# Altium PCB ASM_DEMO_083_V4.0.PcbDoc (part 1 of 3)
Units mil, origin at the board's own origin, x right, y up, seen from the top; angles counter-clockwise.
Board outline 4534.65 x 3225.59 mil, 2 copper layers (Top Layer, Bottom Layer); 192 components, 109 nets, 496 pads, 1295 vias.
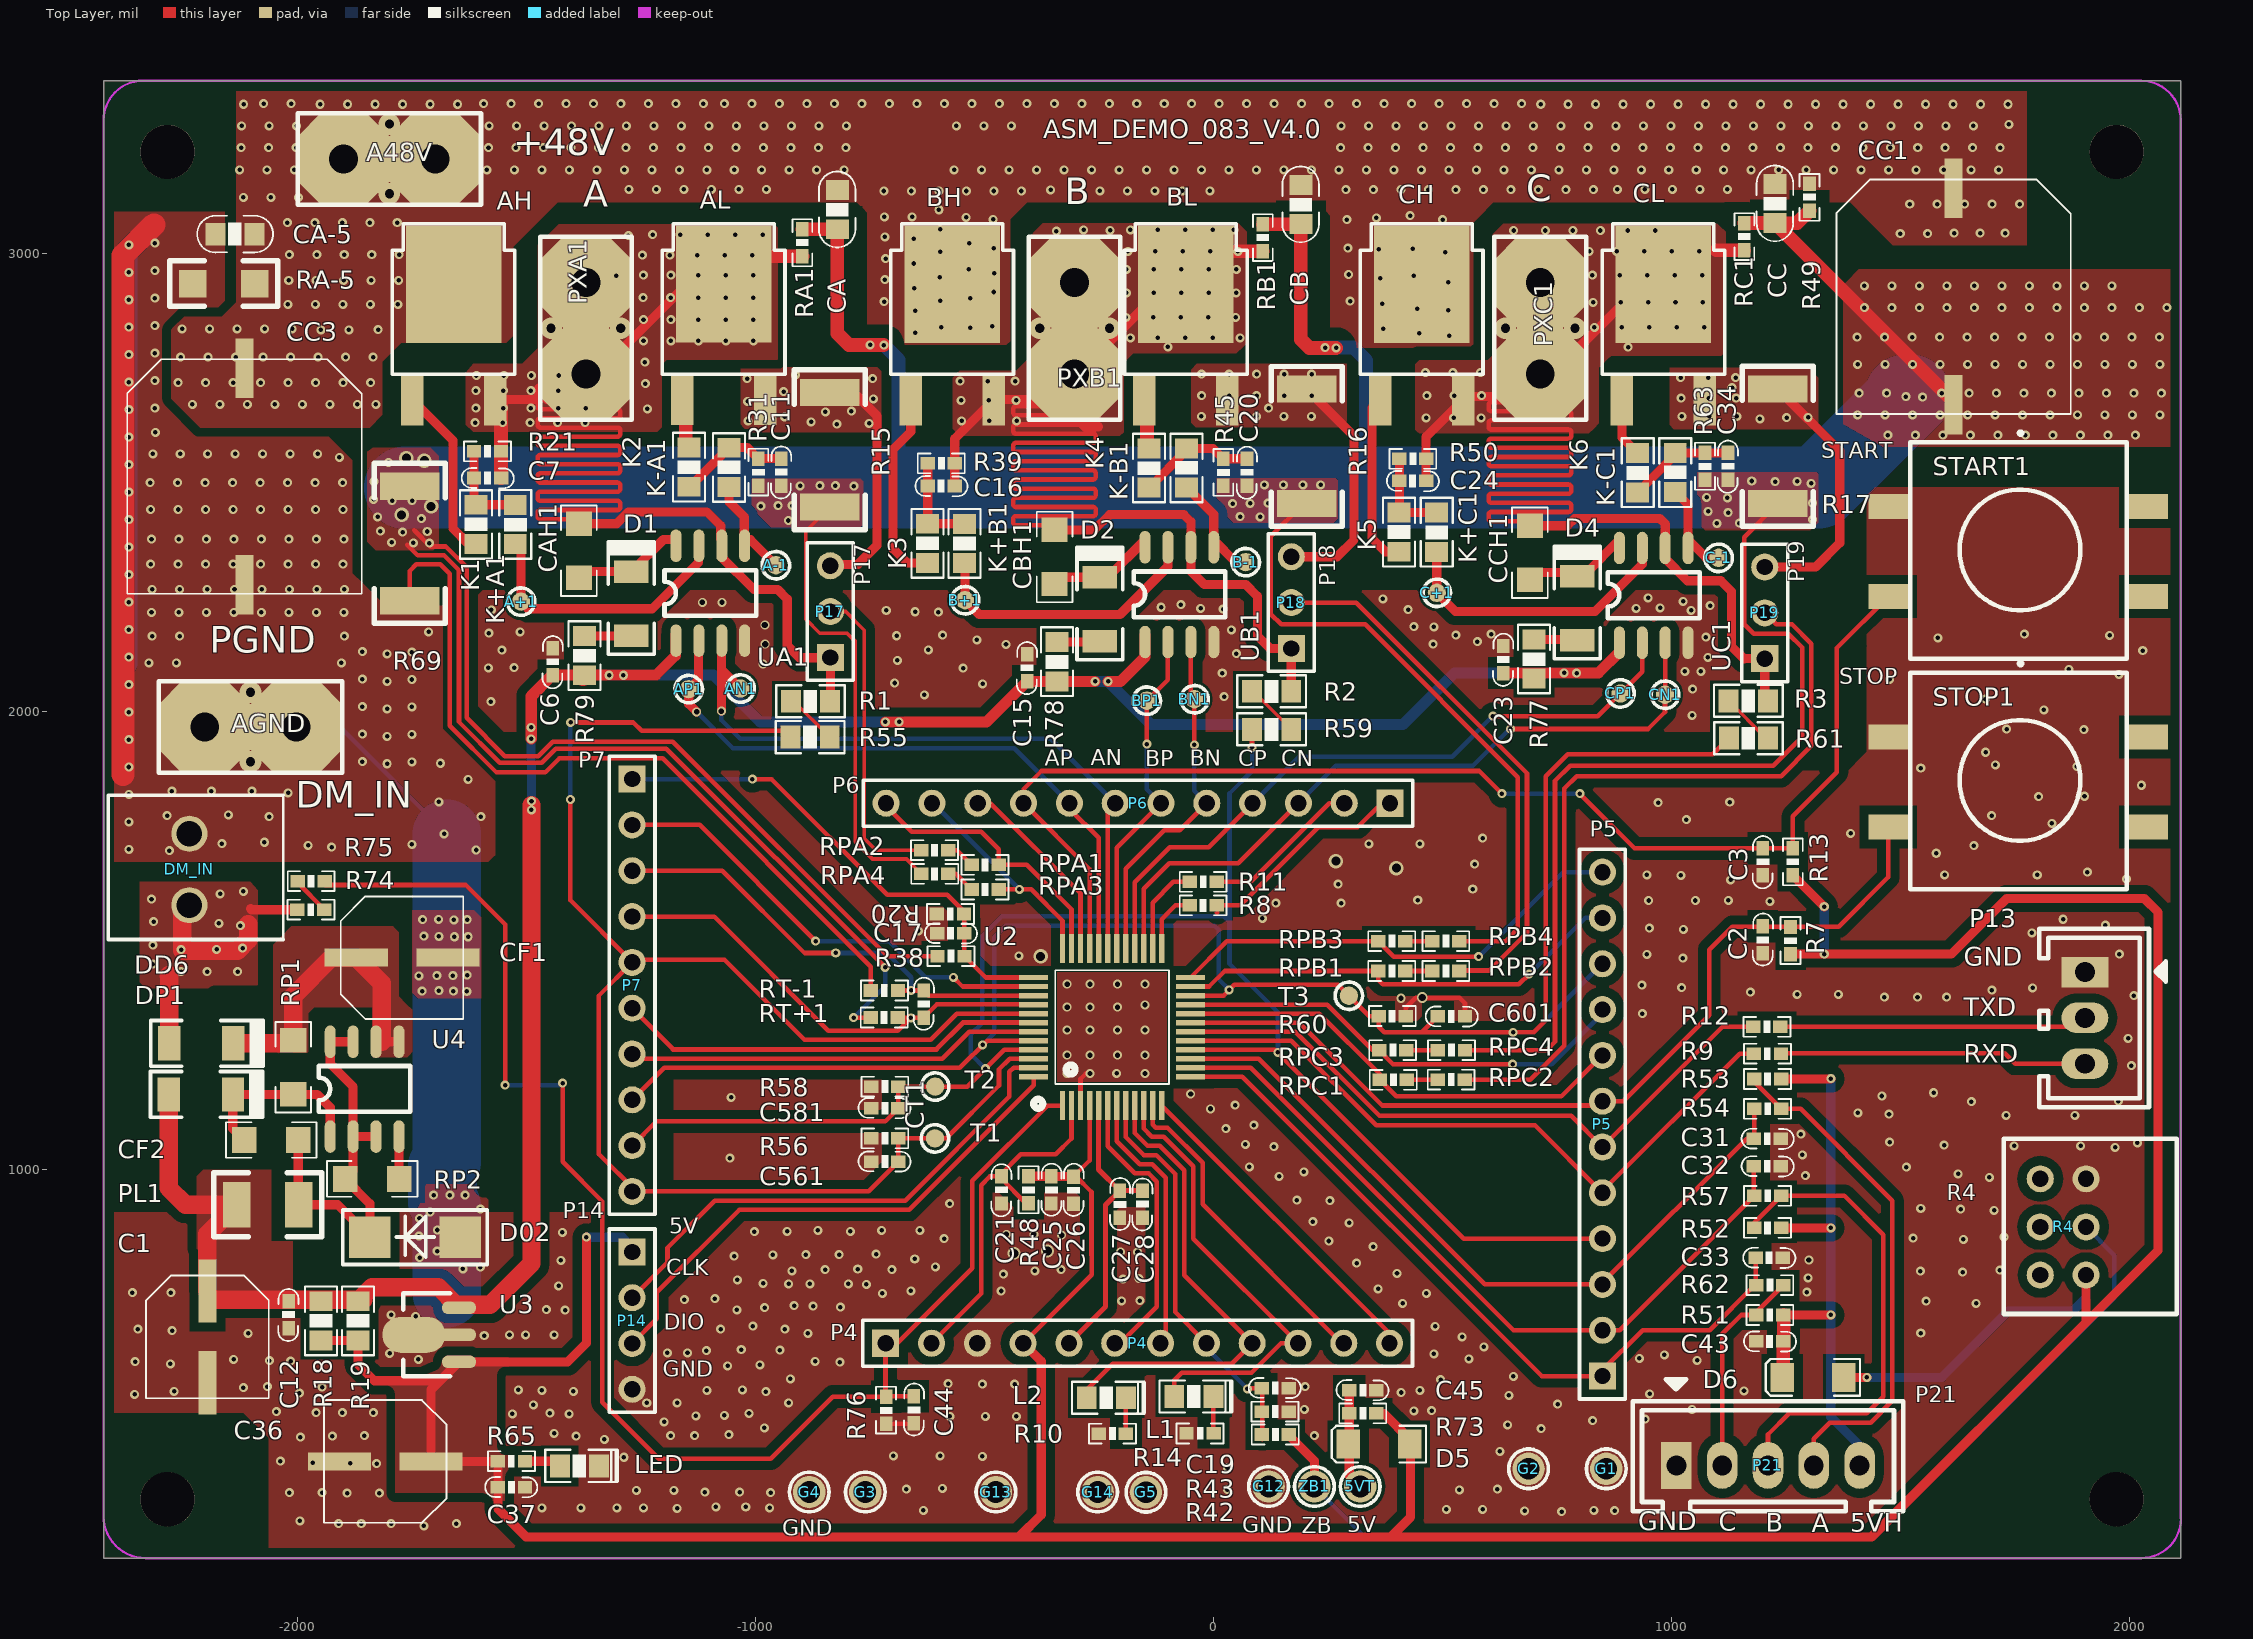
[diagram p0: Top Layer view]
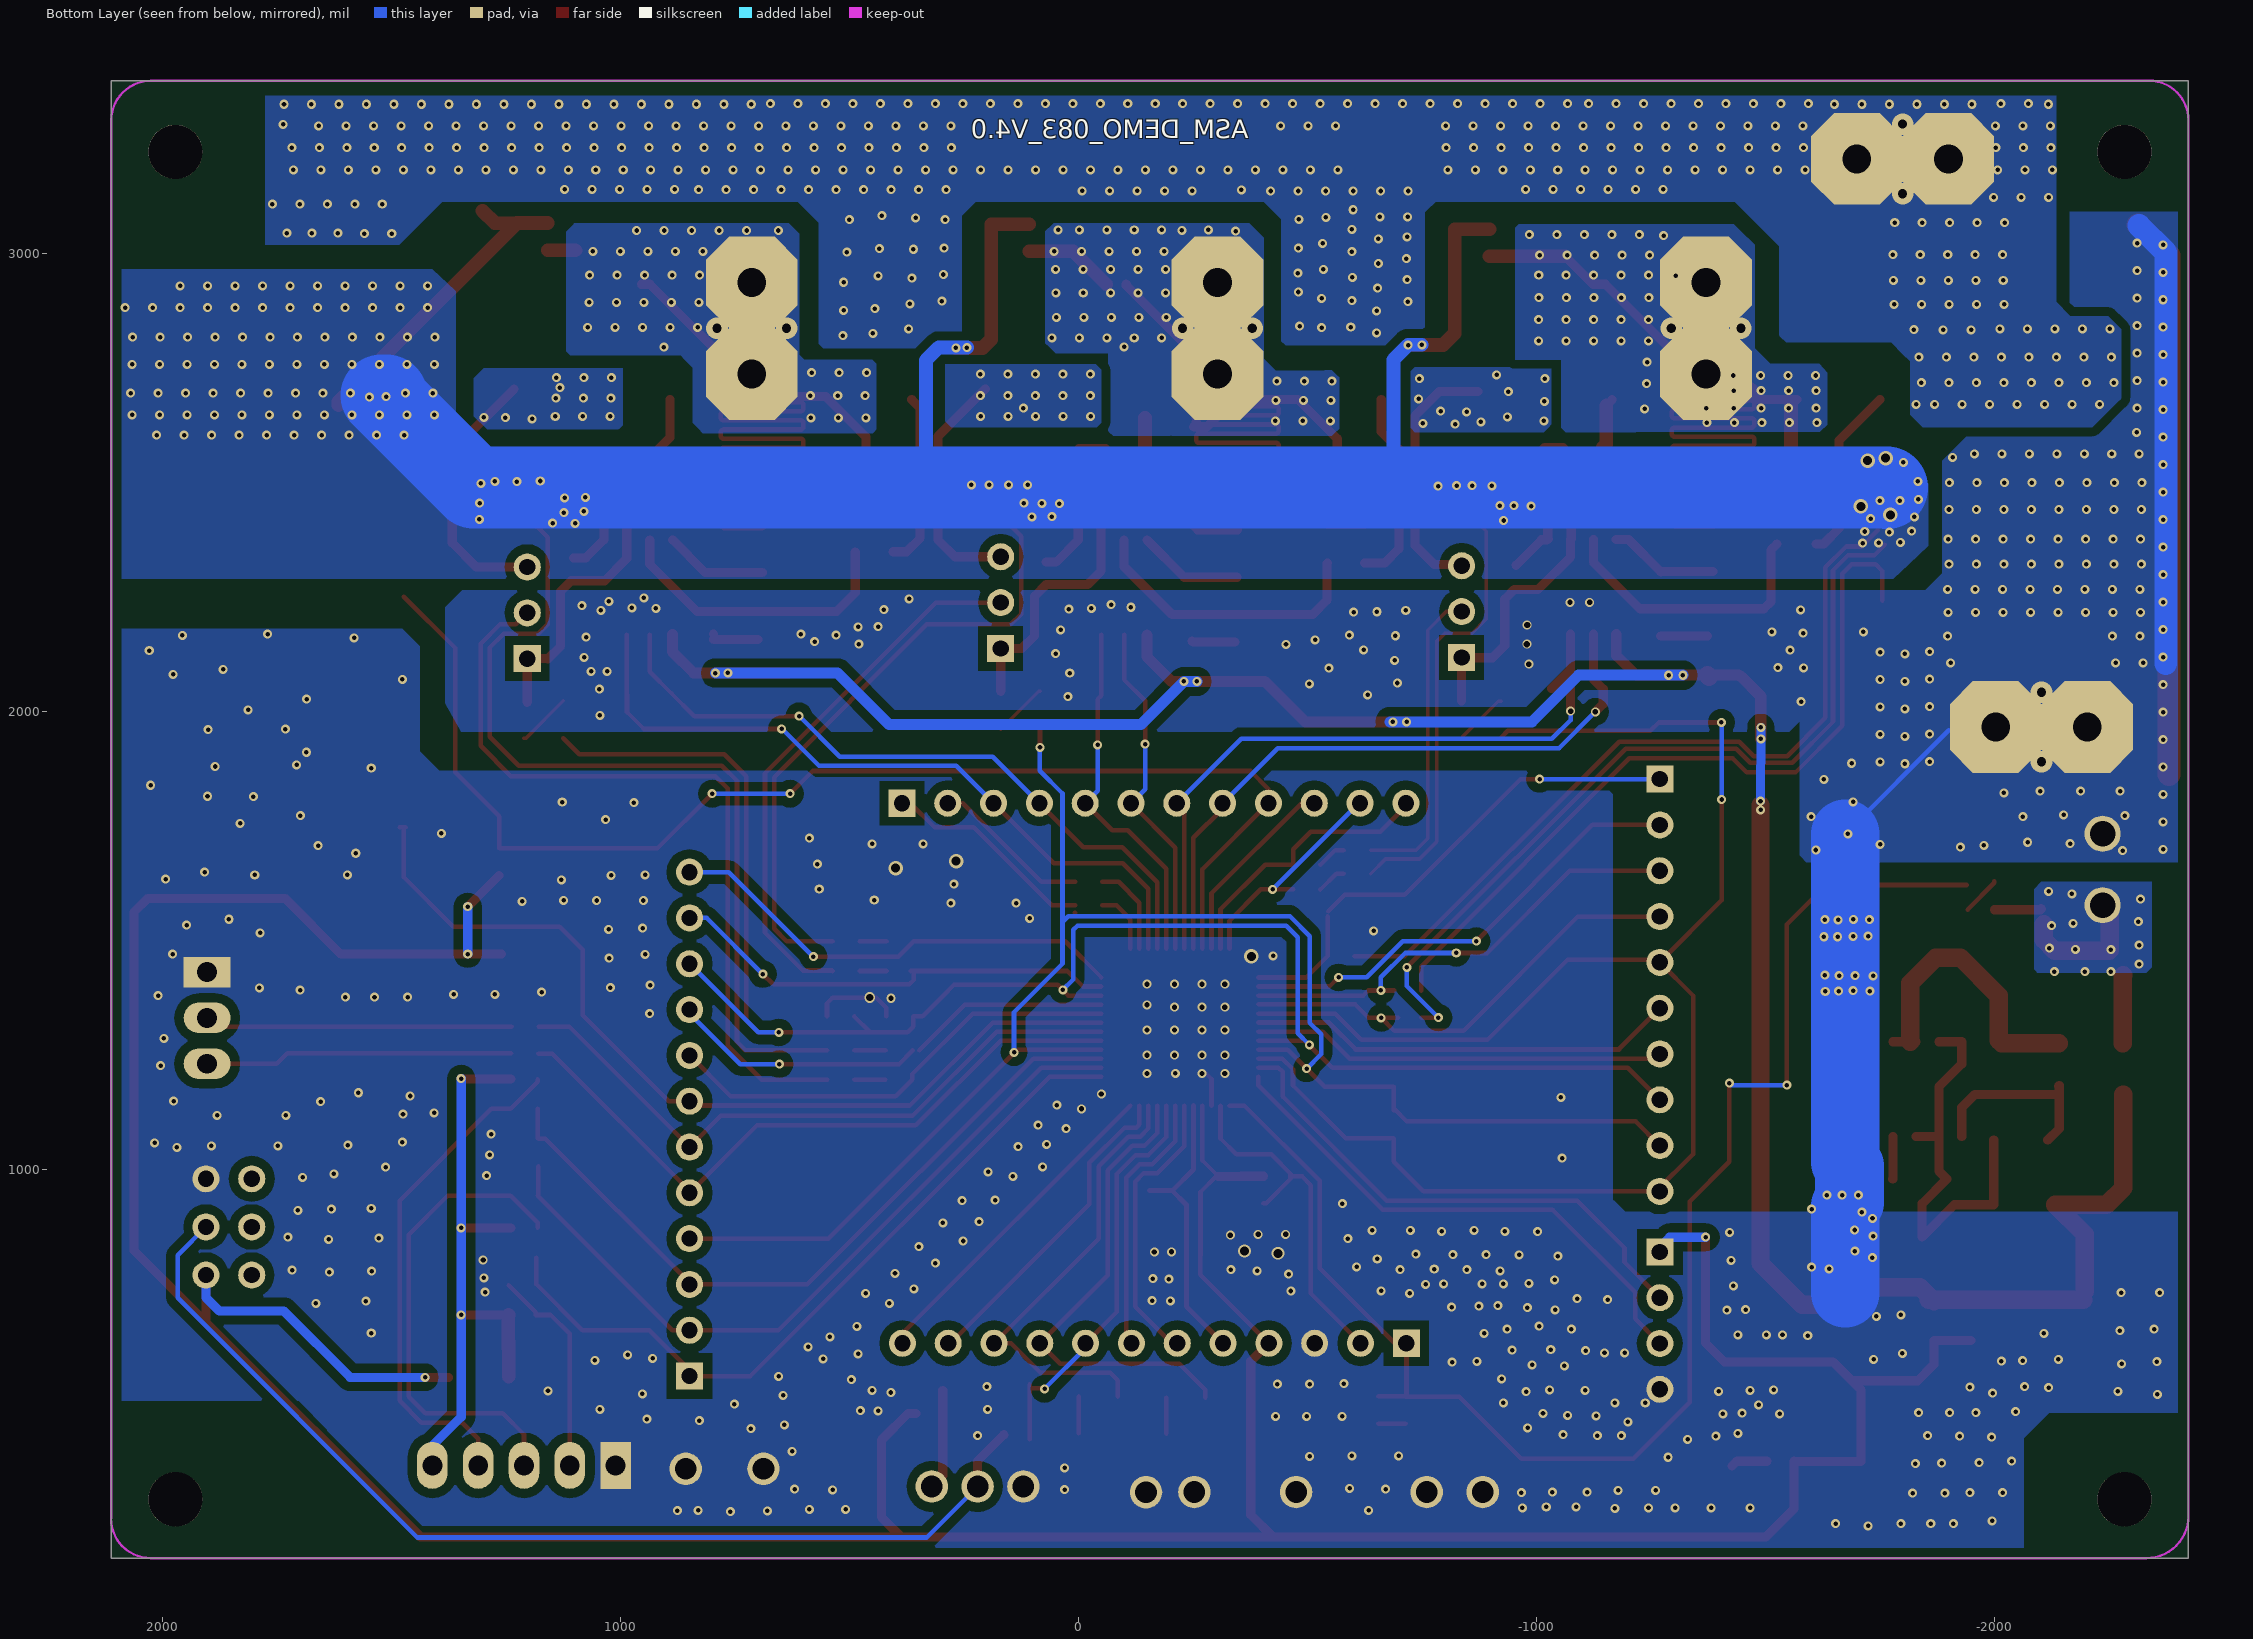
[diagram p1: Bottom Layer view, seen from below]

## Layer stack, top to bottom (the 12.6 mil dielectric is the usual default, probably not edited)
Top Layer: signal copper 1.4
Dielectric: dielectric 12.6, FR-4, Dk 4.8
Bottom Layer: signal copper 1.4

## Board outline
-2422.83,3377.56 2111.81,3377.56 2111.81,151.97 -2422.83,151.97

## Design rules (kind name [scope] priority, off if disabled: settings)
Clearance [InPolygon] p1: gap=20
Clearance Clearance_48V [InNet('+48V')] p2: gap=30
Clearance Clearance_4 [InNet('PGND')] p3 off: gap=20
Clearance Clearance_5V [InNet('+5V')] p4 off: gap=20
Clearance Clearance_15V [InNet('+15V')] p5: gap=20
Clearance Clearance_5 [All] p6: gap=7.87
ComponentClearance [All] p1 off: gap=0 collisioncheckmode=3 verticalgap=0 showdistances=FALSE
MinimumSolderMaskSliver [All] p1 off: minsoldermaskwidth=10
PlaneConnect [All] p1: planeconnectstyle=Direct reliefexpansion=20 reliefentries=4 reliefconductorwidth=10 reliefairgap=10
PolygonConnect [All] p1: connectstyle=Direct reliefconductorwidth=10 reliefentries=4 polygonreliefangle="90 Angle"
RoutingVias [All] p1: holewidth=13.78 width=19.68 viastyle="Through Hole" minholewidth=13.78 minwidth=19.68 maxholewidth=13.78 maxwidth=19.68
SilkToSilkClearance [All] p1 off: silktosilkclearance=10
SilkscreenOverComponentPads SilkToSolderMaskClearance [IsPad] p1 off: minsilkscreentomaskgap=10
SolderMaskExpansion [All] p1: expansion=4
Width Width_2 [All] p1 off: maxlimit=10 minlimit=10 preferedwidth=10
Width Width_1 [InNet('5V-T')] p2 off: maxlimit=40 minlimit=40 preferedwidth=40
Width Width_VH [InNet('5V1')] p3 off: maxlimit=40 minlimit=40 preferedwidth=40
Width Width_5V [InNet('5V')] p4 off: maxlimit=40 minlimit=40 preferedwidth=40
Width Width_14.3V [InNet('+14.3V')] p5 off: maxlimit=50 minlimit=50 preferedwidth=50
Width Width_15V [InNet('+15V')] p6 off: maxlimit=40 minlimit=40 preferedwidth=40
Width Width_48V [InNet('+48V')] p7 off: maxlimit=40 minlimit=40 preferedwidth=40
Width [All] p8: maxlimit=200 minlimit=1 preferedwidth=40
23 further rules are at their usual default settings.

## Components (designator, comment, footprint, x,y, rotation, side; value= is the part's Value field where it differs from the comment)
5VT "" PAD1.2 320.47,308.66 r180 top
A48V "M4" PCRS250S -1798.82,3206.69 r0 top
A+1 "TestP" TP-40 -1511.81,2239.76 r180 top
A-1 "TestP" TP-40 -954.72,2320.08 r0 top
AGND "M4" PCRS250S -2101.97,1966.54 r0 top
AH "A75N75C" TO-252 -1658.66,2807.09 r0 top
AL "A75N75C" TO-252 -1068.9,2807.48 r0 top
AN1 "TestP" TP-40 -1031.89,2050.79 r0 top
AP1 "TestP" TP-40 -1144.88,2049.61 r0 top
B+1 "TestP" TP-40 -541.73,2243.7 r0 top
B-1 "TestP" TP-40 70.87,2326.77 r0 top
BH "A75N75C" TO-252 -570.08,2807.09 r0 top
BL "A75N75C" TO-252 -60.24,2807.09 r0 top
BN1 "TestP" TP-40 -40.94,2027.56 r0 top
BP1 "TestP" TP-40 -144.88,2024.41 r0 top
C1 "220uF/25V  6.3*7.7" "220UF/25V PASTER6.3*7.7" -2196.06,635.04 r0 top (schematic designator C391)
C2 "100nF/50V" 0603C 1199.21,1472.44 r90 top
C3 "100nF/50V" 0603C 1199.61,1701.65 r270 top
C6 "100nF/50V" 0603C -1442.13,2138.19 r270 top
C7 "1nF/50V" 0603C -1614.12,2510.11 r0 top
C11 "1nF/50V" 0603C -943.31,2552.36 r270 top
C12 "100nF/50V" 0603C -2018.9,712.99 r270 top (schematic designator C351)
C15 "100nF/50V" 0603C -406.69,2125.2 r270 top
C16 "1nF/50V" 0603C -623.86,2492.71 r0 top
C17 "1nF/50V" 0603C -603.15,1516.54 r0 top
C19 "100nF/50V" 0603C 164.17,523.23 r180 top
C20 "1nF/50V" 0603C 73.44,2551.81 r270 top
C21 "100nF/50V" 0603C -462.6,985.43 r270 top
C23 "100nF/50V" 0603C 633.07,2143.31 r270 top
C24 "1nF/50V" 0603C 405.33,2503.79 r0 top
C25 "10uF/10V" 0603C -353.94,926.38 r90 top
C26 "100nF/50V" 0603C -305.51,925.98 r90 top
C27 "10uF/10V" 0603C -204.33,895.28 r90 top
C28 "100nF/50V" 0603C -154.72,954.33 r270 top
C31 "10nF/16V" 0603C 1179.76,1068.03 r0 top
C32 "10nF/16V" 0603C 1179.76,1008.03 r0 top
C33 "10nF/16V" 0603C 1183.46,808.03 r0 top
C34 "1nF/50V" 0603C 1123.25,2565.02 r270 top
C36 "220uF/16V" "220UF/16V PASTER6.3*7.7 - DUPLICATE" -1807.87,363.39 r270 top
C37 "100nF/50V" 0603C -1502.76,306.69 r180 top
C43 "100nF/50V" 0603C 1185.04,625.59 r0 top
C44 "100nF/50V" 0603C -653.94,446.46 r90 top
C45 "100nF/50V" 0603C 355.51,518.5 r180 top
C561 "10nF/16V" 0603C -687.8,1017.72 r180 top
C581 "10nF/16V" 0603C -687.8,1134.25 r180 top
C601 "10nF/16V" 0603C 490.16,1335.04 r0 top
C+1 "TestP" TP-40 488.19,2259.06 r270 top
C-1 "TestP" TP-40 1103.15,2336.22 r0 top
CA "100nF/100V" 0805C -820.87,3053.15 r90 top
CA-5 "100nF/100V" 0805C -2178.74,3042.13 r0 top
CAH1 "47uF/25V" 1206#1 -1385.43,2292.52 r90 top
CB "100nF/100V" 0805C 190.93,3064.25 r90 top
CBH1 "47uF/25V" 1206#1 -347.24,2279.13 r90 top
CC "100nF/100V" 0805C 1226.17,3066.43 r90 top
CC1 "220uF/63V" "220UF/25V paster12.5" 1615.75,2905.91 r0 top
CC3 "220uF/63V" "220UF/25V paster12.5" -2114.96,2513.39 r0 top
CCH1 "47uF/25V" 1206#1 690.55,2288.19 r90 top
CF1 "10UF/100V" "220UF/25V PASTER6.3*7.7" -1771.26,1462.99 r90 top
CF2 "10uF/100V" 1206#1 -2115.35,1065.35 r0 top
CH "A75N75C" TO-252 454.72,2807.09 r0 top
CL "A75N75C" TO-252 982.28,2807.09 r0 top
CN1 "TestP" TP-40 986.22,2037.4 r0 top
CP1 "TestP" TP-40 888.98,2040.16 r0 top
CT1 "1uF/10V" 0603C -632.68,1332.28 r90 top
D1 "1N4148" SOD80 -1266.72,2302.68 r270 top
D2 "1N4148" SOD80 -243.7,2290.94 r270 top
D02 "ES1J" DO-214AC -1742.91,853.15 r180 top
D4 "1N4148" SOD80 798.43,2292.91 r270 top
D5 "1N4007" D1206 296.46,402.76 r0 top
D6 "1N4007" D1206 1244.09,548.43 r0 top
DD6 "1N4007" SOD80 -2142.13,1271.65 r180 top
DM_IN "CON2" SIP3.96-2 -2235.43,1655.51 r90 top
DP1 "ES1J" SOD80 -2142.91,1160.24 r180 top
G1 "PAD1.2" PAD1.2 857.65,347.22 r0 top
G2 "PAD1.2" PAD1.2 687.96,347.22 r0 top
G3 "PAD1.2" PAD1.2 -759.84,296.46 r0 top
G4 "PAD1.2" PAD1.2 -882.28,296.46 r0 top
G5 "PAD1.2" PAD1.2 -147.24,296.06 r0 top
G12 "PAD1.2" PAD1.2 120.47,308.66 r0 top
G13 "PAD1.2" PAD1.2 -474.8,296.46 r0 top
G14 "PAD1.2" PAD1.2 -252.76,296.46 r0 top
K1 "1R" 0805R -1609.84,2451.57 r270 top
K2 "1R" 0805R -1144.88,2490.94 r90 top
K3 "1R" 0805R -624.02,2410.24 r270 top
K4 "1R" 0805R -140.45,2489.02 r90 top
K5 "1R" 0805R 405.12,2434.65 r270 top
K6 "1R" 0805R 926.18,2478.7 r90 top
K+A1 "10R" 0805R -1524.02,2365.75 r90 top
K+B1 "10R" 0805R -543.31,2324.41 r90 top
K+C1 "10R" 0805R 487.4,2348.82 r90 top
K-A1 "10R" 0805R -1057.48,2575.98 r270 top
K-B1 "10R" 0805R -58.66,2574.8 r270 top
K-C1 "10R" 0805R 1008.27,2564.96 r270 top
L1 "LED" SOD323 -45.63,507.12 r0 top
L2 "LED" SOD323 -236.61,504.34 r0 top
LED "LED_R" SOD323 -1386.61,355.51 r0 top
P4 "Header 12" HDR1X12 -715.35,621.26 r0 top
P5 "Header 12" HDR1X12 849.21,549.68 r90 top
P6 "Header 12" HDR1X12 385.57,1800.14 r180 top
P7 "Header 10" HDR1X10 -1268.9,1852.76 r270 top
P13 "P13" 2.54-XH-3A-180 1902.36,1431.5 r90 top
P14 "Header 4" HDR1X4 -1268.9,820.76 r270 top
P17 "Header 3" HDR1X3 -836.22,2118.5 r90 top
P18 "Header 3" HDR1X3 170.08,2138.19 r90 top
P19 "Header 3" HDR1X3 1203.54,2115.75 r90 top
P21 "Header 5" 2.54-XH-5A-180 1210.63,354.72 r180 top
PL1 "100uH  6*8  //330uH" 1210 -2130.31,922.83 r0 top
PXA1 "M4" PCRS250S -1369.68,2837.01 r90 top
PXB1 "M4" PCRS250S -303.15,2837.01 r90 top
PXC1 "M4" PCRS250S 713.39,2837.01 r90 top
R1 "20K 1%" 0805R -922.44,2022.83 r0 top
R2 "20K 1%" 0805R 84.25,2044.49 r0 top
R3 "20K 1%" 0805R 1124.8,2023.62 r0 top
R4 "RPot" 电位器 1850,875.2 r270 top
R7 "10K" 0603R 1259.84,1470.87 r90 top
R8 "10R" 0603R -51.97,1577.17 r0 top
R9 "10R" 0603R 1179.92,1253.54 r0 top
R10 "1K1%" 0603R -190.94,424.02 r180 top
R11 "1R" 0603R 7.09,1628.35 r180 top
R12 "10R" 0603R 1237.8,1311.81 r180 top
R13 "10K" 0603R 1265.04,1701.65 r270 top
R14 "1K1%" 0603R 0.39,424.42 r180 top
R15 "0.005R/2512" 2512 -837.4,2694.88 r270 top (schematic designator R301)
R16 "0.005R/2512" 2512 203.15,2455.91 r90 top (schematic designator R302)
R17 "0.005R/2512" 2512 1232.68,2702.76 r270 top (schematic designator R303)
R18 "1.5K" 0805R -1948.03,712.99 r270 top (schematic designator R791)
R19 "1.5K" 0805R -1867.32,712.99 r270 top (schematic designator R761)
R20 "10R" 0603R -603.54,1558.27 r0 top
R21 "20K1%" 0603R -1555.12,2568.11 r180 top
R31 "20K1%" 0603R -993.28,2493.39 r90 top
R38 "1K1%" 0603R -543.31,1466.14 r180 top
R39 "20K1%" 0603R -564.57,2542.13 r180 top
R42 "10K" 0603R 164.46,422.03 r180 top
R43 "20K1%" 0603R 164.17,472.05 r180 top
R45 "20K1%" 0603R 21.65,2492.91 r90 top
R48 "100K" 0603R -403.54,926.77 r90 top
R49 "51K" 0603R 1301.18,3152.36 r270 top
R50 "20K1%" 0603R 464.96,2551.97 r180 top
R51 "2K" 0603R 1185.24,683.03 r0 top
R52 "2K" 0603R 1180.24,873.03 r0 top
R53 "2K" 0603R 1180.24,1198.03 r0 top
R54 "2K" 0603R 1239.29,1133.03 r180 top
R55 "20K 1%" 0805R -923.23,1944.49 r0 top
R56 "1K1%" 0603R -687.8,1068.5 r180 top
R57 "2K" 0603R 1239.29,943.03 r180 top
R58 "1K1%" 0603R -687.8,1181.5 r180 top
R59 "20K 1%" 0805R 84.25,1961.42 r0 top
R60 "1K1%" 0603R 361.02,1335.51 r0 top
R61 "20K 1%" 0805R 1125.2,1942.13 r0 top
R62 "2K" 0603R 1244.29,748.03 r180 top
R63 "20K1%" 0603R 1073.23,2506.3 r90 top
R65 "3.3K" 0603R -1561.81,363.78 r0 top
R69 "KTS" 2512 -1754.33,2490.55 r270 top
R73 "10K" 0603R 355.51,468.11 r180 top
R74 "20K1%" 0603R -1999.61,1567.72 r0 top
R75 "20K1%" 0603R -1999.21,1629.92 r0 top
R76 "1K1%" 0603R -714.57,445.67 r90 top
R77 "10R" 0805R 700,2072.05 r90 top
R78 "10R" 0805R -341.34,2066.14 r90 top
R79 "10R" 0805r -1372.83,2079.53 r90 top
RA1 "51K" 0603R -897.24,3053.15 r270 top
RA-5 "47K" 1206#2 -2160.24,2934.65 r180 top
RB1 "51K" 0603R 107.93,3064.25 r270 top
RC1 "51K" 0603R 1159.06,3066.54 r270 top
RP1 "100K" 1206#1 -2009.06,1164.96 r90 top
RP2 "1R" 1206#1 -1777.56,979.53 r180 top
RPA1 "20K1%" 0603R -527.95,1665.75 r0 top
RPA2 "20K1%" 0603R -638.19,1697.64 r0 top
RPA3 "20K1%" 0603R -527.95,1611.81 r0 top
RPA4 "20K1%" 0603R -637.8,1646.06 r0 top
RPB1 "20K1%" 0603R 418.9,1433.94 r180 top
RPB2 "20K1%" 0603R 537.01,1433.94 r180 top
RPB3 "20K1%" 0603R 418.9,1498.9 r180 top
RPB4 "20K1%" 0603R 537.01,1498.9 r180 top
RPC1 "20K1%" 0603R 422.05,1196.46 r180 top
RPC2 "20K1%" 0603R 548.43,1196.85 r180 top
RPC3 "20K1%" 0603R 420.87,1261.02 r180 top
RPC4 "20K1%" 0603R 549.21,1261.02 r180 top
RT+1 "1K1%" 0603R -748.03,1332.28 r0 top
RT-1 "1K1%" 0603R -747.64,1391.34 r0 top
START1 "SW-PB" "SW-PB  12*12" 1756.69,2349.61 r0 top
STOP1 "SW-PB" "SW-PB  12*12" 1756.69,1846.46 r0 top
T1 "TestP" TP-40 -607.48,1068.9 r0 top
T2 "TestP" TP-40 -607.09,1181.89 r0 top
T3 "TestP" TP-40 296.06,1380.31 r0 top
U2 "ASM31AMC8T8" TQFP48 -329.43,1140.14 r0 top
U3 "LM7805" SOT-89 -1696.06,639.76 r90 top
U4 "LKS611" so-8 -1925.98,1073.23 r90 top
UA1 "LKS560" SO-8 -1171.26,2155.91 r90 top
UB1 "LKS560" SO-8 -147.24,2152.76 r90 top
UC1 "LKS560" SO-8 888.19,2151.18 r90 top
ZB1 "PAD1.2" PAD1.2 220.47,308.66 r0 top

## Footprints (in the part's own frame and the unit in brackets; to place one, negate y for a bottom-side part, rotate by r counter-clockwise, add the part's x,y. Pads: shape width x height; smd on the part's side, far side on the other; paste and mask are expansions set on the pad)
2.54-XH-3A-180 [mm]
  rect 1.7x2.6 hole 1.1: 1(0,0)
  oval 1.7x2.6 hole 1.1: 2(-2.54,0) 3(-5.08,0)
  silkscreen extent -7.49,-4.5 2.41,2.54
2.54-XH-5A-180 [mm]
  rect 1.7x2.6 hole 1.1: 1(5.08,0)
  oval 1.7x2.6 hole 1.1: 2(2.54,0) 3(0,0) 4(-2.54,0) 5(-5.08,0)
  silkscreen extent -7.49,-4.78 7.49,2.54
"220UF/16V PASTER6.3*7.7 - DUPLICATE" [mm]
  rect 1x3.5 smd: 1(0,2.54) 2(0,-2.54)
  silkscreen extent -3.4,-3.4 3.4,3.4
"220UF/25V PASTER6.3*7.7" [mm]
  rect 1x3.5 smd: 1(0,2.54) 2(0,-2.54)
  silkscreen extent -3.4,-3.4 3.4,3.4
"220UF/25V paster12.5" [mm]
  rect 1x3.3 smd: 1(0,6) 2(0,-6)
  silkscreen extent -6.5,-6.5 6.5,6.5
0603C [mm]
  rect 0.8x0.7 smd: 1(0,0) 2(1.5,0)
  silkscreen extent -0.68,-0.57 2.21,0.55
0603R [mm]
  rect 0.8x0.7 smd: 1(0,0) 2(1.5,0)
  silkscreen extent -0.55,-0.55 2.05,0.55
0805C [mm]
  rect 1.1x1.27 smd: 1(0,0) 2(2.175,0)
  silkscreen extent -1,-1.01 3.2,1.03
0805R [mm]
  rect 1.1x1.27 smd: 1(0,0) 2(2.175,0)
  silkscreen extent -0.81,-0.89 3,0.89
0805r [mm]
  rect 1.1x1.27 smd: 1(0,0) 2(2.175,0)
  silkscreen extent -0.81,-0.89 3,0.89
1206#1 [mm]
  rect 1.35x1.45 smd: 1(-0.01,-0.01) 2(2.99,-0.01)
  silkscreen extent -1.02,-1 4,0.98
1206#2 [mm]
  rect 1.524x1.524 smd: 1(-1.714,0) 2(1.714,0)
  silkscreen extent -2.98,-1.27 2.98,1.27
1210 [mm]
  rect 1.524x2.54 smd: 1(-0.04,0.02) 2(3.389,0.02)
  silkscreen extent -1.31,-1.76 4.66,1.8
2512 [mm]
  rect 1.5x3.3 smd: 1(-0.04,-0.01) 2(6.31,-0.01)
  silkscreen extent -1.31,-1.98 7.56,1.96
D1206 [mm]
  rect 1.3x1.6 smd: 1(3.346,-0.04) 2(-0.054,-0.04)
  silkscreen extent -0.97,-1.06 4.26,0.98
DO-214AC [mm]
  rect 2.3x2.3 smd: 1(-2.502,0) 2(2.502,0)
  silkscreen extent -4,-1.5 4,1.52
HDR1X3 [mm]
  rect 1.5x1.5 hole 0.9: 1(0,0)
  round 1.5 hole 0.9: 2(2.54,0) 3(5.08,0)
  silkscreen extent -1.27,-1.27 6.35,1.27
HDR1X4 [mm] "Connector; Header; 4 Position"
  rect 1.5x1.5 hole 0.9: 1(0,0)
  round 1.5 hole 0.9: 2(2.54,0) 3(5.08,0) 4(7.62,0)
  silkscreen extent -1.27,-1.27 8.89,1.27
HDR1X10 [mm] "Connector; Header; 10 Position"
  rect 1.5x1.5 hole 0.9: 1(0,0)
  round 1.5 hole 0.9: 2(2.54,0) 3(5.08,0) 4(7.62,0) 5(10.16,0) 6(12.7,0) 7(15.24,0) 8(17.78,0) 9(20.32,0) 10(22.86,0)
  silkscreen extent -1.27,-1.27 24.13,1.27
HDR1X12 [mm] "Connector;"
  rect 1.5x1.5 hole 0.9: 1(0,0)
  round 1.5 hole 0.9: 2(2.54,0) 3(5.08,0) 4(7.62,0) 5(10.16,0) 6(12.7,0) 7(15.24,0) 8(17.78,0) 9(20.32,0) 10(22.86,0) 11(25.4,0) 12(27.94,0)
  silkscreen extent -1.27,-1.27 29.21,1.27
PAD1.2 [mm]
  round 1.8 hole 1.2: 1(0,0)
  silkscreen extent -1.1,-1.1 1.1,1.1
PCRS250S [mm]
  oct 5.08x5.08 hole 1.6: 1(-2.54,0) 1(2.54,0)
  silkscreen extent -5.08,-2.54 5.08,2.54
SIP3.96-2 [mm]
  round 2 hole 1.4: 1(-1.98,0) 2(1.98,0)
  silkscreen extent -3.88,-5.21 4.12,4.5
so-8 [mm]
  oval 1.8x0.61 smd: 1(-0.02,0.05) 2(-0.02,-1.22) 3(-0.02,-2.49) 4(-0.02,-3.76) 5(5.238,-3.76) 6(5.238,-2.49) 7(5.238,-1.22) 8(5.238,0.05)
  silkscreen extent 1.35,-4.4 3.89,0.68
SO-8 [mm]
  oval 1.8x0.61 smd: 1(-0.02,0.05) 2(-0.02,-1.22) 3(-0.02,-2.49) 4(-0.02,-3.76) 5(5.238,-3.76) 6(5.238,-2.49) 7(5.238,-1.22) 8(5.238,0.05)
  silkscreen extent 1.35,-4.4 3.89,0.68
SOD80 [mil]
  rect 49x75 smd: 1(137.32,-4.18) 2(-2.68,-4.18)
  silkscreen extent -68,-54 177,46
SOD323 [mil]
  rect 43.31x50 smd: 1(-40,-2) 2(45.63,-2)
  silkscreen extent -72,-37 87,33
SOT-89 [mm]
  oval 0.7x1.9 smd: 1(-1.5,-1.25) 3(1.5,-1.25)
  oval 2x3.5 smd: 2(0,1.25)
  oval 0.7x2.1 smd: 2(0,-1.15)
  silkscreen extent -2.3,-0.75 2.3,1.85
"SW-PB  12*12" [mm]
  rect 2.2x1.397 smd: 1(-7.2,2.5) 2(-7.2,-2.5) 3(7.2,2.5) 4(7.2,-2.5)
  silkscreen extent -5.98,-5.94 6.02,6.68
TO-252 [mm]
  rect 1.25x2.85 smd: 1(-2.3,-3.2) 3(2.3,-3.2)
  rect 5.3x6.5 smd: 2(0,3.2)
  silkscreen extent -3.4,-1.8 3.4,6.55
TP-40 [mil]
  round 40 smd: 1(-0.39,-0.39)
  silkscreen extent -30,-30 29,30
TQFP48 [mm]
  rect 0.3x1.6 smd: 1(0,0) 2(0.5,0) 3(1,0) 4(1.5,0) 5(2,0) 6(2.5,0) 7(3,0) 8(3.5,0) 9(4,0) 10(4.5,0) 11(5,0) 12(5.5,0) 25(5.5,8.7) 26(5,8.7) 27(4.5,8.7) 28(4,8.7) 29(3.5,8.7) 30(3,8.7) 31(2.5,8.7) 32(2,8.7) 33(1.5,8.7) 34(1,8.7) 35(0.5,8.7) 36(0,8.7)
  rect 1.6x0.3 smd: 13(7.1,1.6) 14(7.1,2.1) 15(7.1,2.6) 16(7.1,3.1) 17(7.1,3.6) 18(7.1,4.1) 19(7.1,4.6) 20(7.1,5.1) 21(7.1,5.6) 22(7.1,6.1) 23(7.1,6.6) 24(7.1,7.1) 37(-1.6,7.1) 38(-1.6,6.6) 39(-1.6,6.1) 40(-1.6,5.6) 41(-1.6,5.1) 42(-1.6,4.6) 43(-1.6,4.1) 44(-1.6,3.6) 45(-1.6,3.1) 46(-1.6,2.6) 47(-1.6,2.1) 48(-1.6,1.6)
  silkscreen extent -1.6,-0.15 5.9,7.5
电位器 [mm]
  round 1.5 hole 0.9: 1(2.667,1.397) 2(-2.667,1.397) 3(0,1.397) 4(-2.667,-1.143) 5(0,-1.143) 6(2.667,-1.143)
  silkscreen extent -4.89,-3.18 4.83,6.41

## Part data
A48V AGND PXA1 PXB1 PXC1: library part S
C1 C36 CC3: library part CD, "Electro"
C561 C581 C601: library part CAP, "Capacitor"
CAH1 CBH1 CC1 CCH1: library part "Cap Pol1", "Polarized Cap"
CF1: library part CD, "Electrolytic Capacitor"
CF2: library part Cap, "Capacitor"
D1 D2 D4: library part Diode
D02 DD6: library part D, "Diode"
D5 D6 DP1: library part "Diode 1N4007", "1 Amp General Purpose Rectifier"
DM_IN: "Connector"
G1 G2 G3 G4 G5 G12 G13 G14: library part CON1, "Connector"
LED: library part LED
P4: "Header, 12-Pin"
P7: "Header, 10-Pin"
P13: library part "Header 3"
P14: "Header, 4-Pin"
P21: "Header, 5-Pin"
PL1: library part L
R1 R2 R3: library part RES/1
R4: "Potenti"
R18 R19: library part R-2W, "1W或2W功"
R20 R38 R42 R43 R48 R69 R74 R75 R76 RA-5 RPA1 RPA2 RPA3 RPA4 RPB1 RPB2 RPB3 RPB4 RPC1 RPC2 RPC3 RPC4 RT+1 RT-1: library part R
R77 R78: library part RE
R79: library part RES2短
RP1 RP2: library part Res2, "Resistor"
START1 STOP1: "Switch"
U2: library part LKS0

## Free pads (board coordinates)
  round 118.11 hole 118.11: 0(1971.65,3222.05) 1(-2283.07,3222.05) 2(1971.65,280.71) 3(-2283.07,280.71)

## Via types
v1: diameter 19.68, hole 9.84, Top Layer to Bottom Layer, 1240 vias
v2: diameter 19.68, hole 11.81, Top Layer to Bottom Layer, 33 vias
v3: diameter 47.24, hole 20, Top Layer to Bottom Layer, 10 vias
v4: diameter 31.5, hole 19.68, Top Layer to Bottom Layer, 7 vias
v5: diameter 27.56, hole 19.68, Top Layer to Bottom Layer, 2 vias
v6: diameter 19.68, hole 13.78, Top Layer to Bottom Layer, 2 vias
v7: diameter 23.62, hole 15.75, Top Layer to Bottom Layer, 1 vias

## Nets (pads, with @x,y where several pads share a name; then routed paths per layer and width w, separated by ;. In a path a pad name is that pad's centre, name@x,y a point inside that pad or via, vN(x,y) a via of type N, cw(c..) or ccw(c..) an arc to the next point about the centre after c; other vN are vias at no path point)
5V-T: 5VT.1 C45.2 D5.2 R73.2 | length 219.8
  Top Layer w20: D5.2@296.46,402.76 296.46,332.68 5VT.1@320.47,308.66 ; D5.2@296.61,402.76 C45.2@296.61,518.5
5VH: C43.2 D6.2 P21.5 R51.2 R52.2 R53.2 | length 1341.1
  Top Layer w20: R52.2@1239.29,873.03 v1(1347.68,873.03) ; R53.2@1239.29,1198.03 v1@1347.68,1198.03 ; R51.2@1244.29,683.03 v1(1347.68,683.03)
  Top Layer w30: D6.2@1244.09,548.43 C43.2@1244.09,625.59 ; R51.2@1244.29,683.03 1245.28,682.05 1245.28,610.24
  Bottom Layer w20: v1(1347.68,1199.21) v1(1347.68,873.03) v1(1347.68,683.03) 1347.68,460.59 1410.63,397.64 P21.5@1410.63,354.72
+5V: C25.2 C26.2 C36.1 C37.2 D5.1 D6.1 P4.4 P14.1 R4.1 R7.1 R13.2 R18.2 R19.2 R48.2 R65.1 R73.1 U2.4 U3.1 | length 9420.5
  Top Layer w10: P4.4@-415.35,621.26 -265.93,770.68 -265.93,812.99 -266.14,813.2 -266.14,951.5 -299.68,985.04 C26.2@-305.51,985.04 -304.23,986.32 -270.37,1020.18 U2.4@-270.37,1140.14
  Top Layer w20: R18.2@-1948.03,627.36 R19.2@-1867.32,627.36 -1867.32,575.2 -1831.5,539.37 -1688.19,539.37 ; v1(-1368.86,852.76) -1368.86,621.65 -1409.8,580.71 U3.1@-1646.85,580.71 -1688.19,539.37 ; P4.4@-415.35,621.26 -375.98,581.89 -375.98,246.85 -424.41,198.43 ; R48.2@-403.54,985.83 -354.33,985.83 C25.2@-353.94,985.43 -305.91,985.43 C26.2@-305.51,985.04 ; R73.1@355.51,468.11 372.2,468.11 430.31,410 430.31,241.73 387.01,198.43 ; R7.1@1259.84,1470.87 v1(1333.46,1470.87) 1610.63,1470.87 1731.89,1592.13 2031.89,1592.13 2062.2,1561.81 2062.2,824.02 1905,666.81 ; R13.2@1265.04,1642.6 v1(1333.46,1574.17) ; D6.1@1375.83,546.85 v1(1426.57,546.85) ; R4.1@1905,770.2 1905,666.81 ; -1688.19,539.37 -1707.87,519.68 C36.1@-1707.87,363.39 -1562.2,363.39 R65.1@-1561.81,363.78 C37.2@-1561.81,306.69 -1561.81,259.84 -1500.39,198.43 -424.41,198.43 ; -424.41,198.43 387.01,198.43 ; 387.01,198.43 1436.61,198.43 1905,666.81
  Bottom Layer w20: v1(-1368.86,852.76) -1290.17,852.76 P14.1@-1269.17,831.76 ; v1(1333.46,1470.87) v1(1333.46,1574.17) ; v1(1426.57,546.85) 1590.16,546.85 1735.04,691.73 1875.59,691.73 1905,721.14 R4.1@1905,770.2
+15V: C1.1 C6.2 C12.1 C15.2 C23.2 DP1.1 PL1.1 R18.1 R19.1 R77.1 R78.1 R79.1 U3.3 UA1.1 UB1.1 UC1.1 | length 5791.3
  Top Layer w24: C6.2@-1442.13,2079.13 -1441.73,2079.53 R79.1@-1372.83,2079.53 v1(-1318.9,2079.53) v1(-1288.19,2079.53) -1217.32,2079.53 -1173.69,2123.16 UA1.1@-1173.69,2168.9 ; v1(-716.13,1977.57) -495.26,1977.57 C15.2@-406.69,2066.14 R78.1@-341.34,2066.14 v1(-258.27,2066.14) ; v1(-229.92,2066.14) -202.36,2066.14 -149.21,2119.29 UB1.1@-149.21,2167.72 ; C23.2@633.07,2084.25 840.16,2084.25 886.22,2130.31 UC1.1@886.22,2168.11
  Top Layer w25: v1(-1489.37,1940.55) -1489.37,2033.86 C6.2@-1446.85,2076.38
  Top Layer w40: DP1.1@-2280.62,1164.42 -2280.62,960.54 -2243.7,923.62 PL1.1@-2131.89,923.62 -2196.06,859.45 C1.1@-2196.06,735.04 ; C1.1@-2193.7,716.54 R19.1@-1863.78,716.54 ; R19.1@-1867.32,712.99 R19.1@-1863.78,716.54 ; R19.1@-1855.51,716.54 R19.1@-1863.78,716.54 ; v1@-1488.58,1795.94 -1488.58,795.67 -1579.13,705.12 -1653.15,705.12 -1691.73,743.7 -1836.61,743.7 R19.1@-1863.78,716.54 ; R79.1@-1375.98,2076.38 R79.1@-1372.83,2079.53
  Bottom Layer w20: v1(-1489.37,1965.75) v1(-1488.58,1804.72)
  Bottom Layer w24: v1(-1318.9,2079.53) v1(-1288.19,2079.53) -1091.73,2079.53 -990.16,1977.95 v1@-679.53,1977.95 ; v1(-258.27,2066.14) v1(-229.92,2066.14) -136.22,1972.44 414.17,1972.44 525.98,2084.25 v1(792.91,2084.25)
  other v1: -1488.98,1785.43 -685.83,1977.56 765.75,2084.65
+48V: A48V.1 AH.2 BH.2 CA-5.2 CA.2 CB.2 CC1.1 CC3.1 CC.2 CH.2 R49.1 RA-5.1
  other v1: -2228.74,2670.87 -2168.74,2670.87 -2108.74,2670.87 -2048.74,2670.87 -1988.74,2670.87 -1928.74,2670.87 -1868.74,2670.87 -1828.35,2670.87 -2259.84,2718.5 -2199.84,2718.5 -2139.84,2718.5 -2079.84,2718.5 -2019.84,2718.5 -1959.84,2718.5 -1899.84,2718.5 -1839.84,2718.5 -2254.33,2774.02 -2194.33,2774.02 -2134.33,2774.02 -2074.33,2774.02 -2014.33,2774.02 -1954.33,2774.02 -1894.33,2774.02 -1834.33,2774.02 514.57,2820.87 449.21,2825.59 -650.39,2826.77 -1948.43,2833.46 -1887.01,2833.46 -1823.23,2834.25 -2251.18,2835.83 -2191.18,2835.83 -2131.18,2835.83 -2071.18,2835.83 -2011.18,2835.83 370.87,2835.83 -530.71,2838.58 -594.09,2839.37 -482.28,2841.73 -650.79,2874.8 512.99,2875.98 444.49,2879.92 -2020.47,2888.98 -1960.47,2888.98 -1900.47,2888.98 -1840.47,2888.98 -1780.47,2888.98 368.5,2890.16 -718.9,2894.88 298.43,2896.46 -596.46,2897.24 -530.71,2901.97 -479.53,2916.14 -652.76,2924.8 512.99,2937.4 -2018.5,2941.34 -1958.5,2941.34 -1898.5,2941.34 -1838.5,2941.34 -1778.5,2941.34 -716.93,2943.31 363.78,2946.46 -597.64,2948.03 437.4,2951.18 295.28,2954.33 -478.74,2957.48 -534.25,2965.35 -654.33,2978.35 -715.75,2988.98 -2017.32,2997.64 -1957.32,2997.64 -1897.32,2997.64 -1837.32,2997.64 -1777.32,2997.64 505.91,3003.15 -596.46,3004.33 360.63,3009.45 435.04,3011.02 -479.53,3011.81 293.7,3011.81 -532.68,3022.44 -654.33,3031.89 -716.93,3036.22 1499.37,3043.7 1559.37,3043.7 1616.93,3044.88 1673.62,3044.88 1728.35,3044.88 -596.46,3052.76 -2021.65,3067.72 -1961.65,3067.72 -1901.65,3067.72 -1841.65,3067.72 -1781.65,3067.72 -480.71,3074.41 291.34,3074.02 500.39,3074.02 355.91,3077.95 -539.76,3079.13 -718.11,3079.92 -657.87,3080.32 429.53,3083.07 -599.21,3095.67 1520.08,3107.87 1580.08,3107.87 1640.08,3107.87 1700.08,3107.87 1760.08,3107.87 -2117.64,3122.44 -2057.64,3122.44 -1997.64,3122.44 -719.13,3136.61 -659.13,3136.61 -599.13,3136.61 -539.13,3136.61 -479.13,3136.61 -419.13,3136.61 -247.64,3137.01 -187.64,3137.01 -127.64,3137.01 -67.64,3137.01 -7.64,3137.01 -355.51,3138.98 -1275.83,3140.16 -1215.83,3140.16 -1155.83,3140.16 -1095.83,3140.16 -1035.83,3140.16 -975.83,3140.16 289.37,3139.76 349.37,3139.76 409.37,3139.76 469.37,3139.76 529.37,3139.76 589.37,3139.76 649.37,3139.76 709.37,3139.76 769.37,3139.76 829.37,3139.76 881.89,3140.16 941.89,3140.16 1001.89,3140.16 1061.89,3140.16 1121.89,3140.16 -2125.98,3182.68 -2065.98,3182.68 -2005.98,3182.68 -1585.98,3182.68 -1525.98,3182.68 -1465.98,3182.68 -1405.98,3182.68 -1345.98,3182.68 -1285.98,3182.68 -1225.98,3182.68 -1165.98,3182.68 -1105.98,3182.68 -1045.98,3182.68 -985.98,3182.68 -925.98,3182.68 -865.98,3182.68 -805.98,3182.68 -565.98,3182.68 -505.98,3182.68 -445.98,3182.68 -385.98,3182.68 -325.98,3182.68 -265.98,3182.68 -205.98,3182.68 -145.98,3182.68 -85.98,3182.68 -25.98,3182.68 34.02,3182.68 94.02,3182.68 154.02,3182.68 214.02,3182.68 274.02,3182.68 334.02,3182.68 394.02,3182.68 454.02,3182.68 514.02,3182.68 574.02,3182.68 634.02,3182.68 694.02,3182.68 754.02,3182.68 814.02,3182.68 874.02,3182.68 934.02,3182.68 994.02,3182.68 1054.02,3182.68 1114.02,3182.68 1174.02,3182.68 1234.02,3182.68 1294.02,3182.68 1354.02,3182.68 1414.02,3182.68 1474.02,3182.68 1534.02,3182.68 1594.02,3182.68 1654.02,3182.68 1714.02,3182.68 -2122.44,3231.1 -2062.44,3231.1 -2002.44,3231.1 -1582.44,3231.1 -1522.44,3231.1 -1462.44,3231.1 -1402.44,3231.1 -1342.44,3231.1 -1282.44,3231.1 -1222.44,3231.1 -1162.44,3231.1 -1102.44,3231.1 -1042.44,3231.1 -982.44,3231.1 -922.44,3231.1 -862.44,3231.1 -802.44,3231.1 277.56,3231.1 337.56,3231.1 397.56,3231.1 457.56,3231.1 517.56,3231.1 577.56,3231.1 637.56,3231.1 697.56,3231.1 757.56,3231.1 817.56,3231.1 877.56,3231.1 937.56,3231.1 997.56,3231.1 1057.56,3231.1 1117.56,3231.1 1177.56,3231.1 1237.56,3231.1 1297.56,3231.1 1357.56,3231.1 1417.56,3231.1 1477.56,3231.1 1537.56,3231.1 1597.56,3231.1 1657.56,3231.1 1717.56,3231.1 -2121.26,3278.74 -2061.26,3278.74 -2001.26,3278.74 -1581.26,3278.74 -1521.26,3278.74 -1461.26,3278.74 -1401.26,3278.74 -1341.26,3278.74 -1281.26,3278.74 -1221.26,3278.74 -1161.26,3278.74 -1101.26,3278.74 -1041.26,3278.74 -981.26,3278.74 -921.26,3278.74 -861.26,3278.74 -801.26,3278.74 -561.26,3278.74 -501.26,3278.74 -441.26,3278.74 278.74,3278.74 338.74,3278.74 398.74,3278.74 458.74,3278.74 518.74,3278.74 578.74,3278.74 638.74,3278.74 698.74,3278.74 758.74,3278.74 818.74,3278.74 878.74,3278.74 938.74,3278.74 998.74,3278.74 1058.74,3278.74 1118.74,3278.74 1178.74,3278.74 1238.74,3278.74 1298.74,3278.74 1358.74,3278.74 1418.74,3278.74 1478.74,3278.74 1538.74,3278.74 1598.74,3278.74 1658.74,3278.74 1736.61,3282.28 -2116.93,3325.98 -1950,3325.98 -1890,3325.98 -1830,3325.98 -1770,3325.98 -1710,3325.98 -1650,3325.98 714.57,3325.98 774.57,3325.98 834.57,3325.98 894.57,3325.98 954.57,3325.98 1014.57,3325.98 1074.57,3325.98 1134.57,3325.98 1194.57,3325.98 1254.57,3325.98 1314.57,3325.98 1374.57,3325.98 1434.57,3325.98 1494.57,3325.98 1554.57,3325.98 1614.57,3325.98 1674.57,3325.98 1734.57,3325.98 -2073.23,3327.17 -2013.23,3327.17 -1593.23,3327.17 -1533.23,3327.17 -1473.23,3327.17 -1413.23,3327.17 -1353.23,3327.17 -1293.23,3327.17 -1233.23,3327.17 -1173.23,3327.17 -1113.23,3327.17 -1067.32,3327.17 -1007.32,3327.17 -947.32,3327.17 -887.32,3327.17 -827.32,3327.17 -767.32,3327.17 -707.32,3327.17 -647.32,3327.17 -587.32,3327.17 -527.32,3327.17 -467.32,3327.17 -407.32,3327.17 -347.32,3327.17 -287.32,3327.17 -227.32,3327.17 -167.32,3327.17 -107.32,3327.17 -47.32,3327.17 12.68,3327.17 72.68,3327.17 132.68,3327.17 192.68,3327.17 252.68,3327.17 312.68,3327.17 372.68,3327.17 432.68,3327.17 492.68,3327.17 552.68,3327.17 612.68,3327.17 672.68,3327.17
  other v3: -1798.82,3130.69 -1798.82,3282.69
A_N: AN1.1 P6.7 U2.31 UA1.3 | length 1519.9
  Top Layer w10: U2.31@-231,1482.66 -231,1783.57 P6.7@-214.43,1800.14
  Top Layer w20: v2(-1074.02,2001.18) -1073.69,2001.5 -1073.69,2091.8 ; UA1.3@-1073.69,2168.9 -1073.69,2091.8 ; AN1.1@-1032.28,2050.39 -1073.69,2091.8
  Bottom Layer w10: v2(-1074.02,2001.18) -1074.02,1981.72 -1033.24,1940.94 -355.23,1940.94 P6.7@-214.43,1800.14 ; P6.7@-214.43,1786.94 P6.7@-214.43,1801.79
A_N-: A-1.1 K-A1.2 UA1.5 | length 221.4
  Top Layer w20: K-A1.2@-1057.48,2490.35 -1057.48,2458.27 -1024.31,2425.09 UA1.5@-1024.31,2376.51 ; UA1.5@-1025.09,2377.3 -1023.09,2375.29 -1010.72,2375.29 A-1.1@-955.12,2319.68
A_P: AP1.1 P6.8 U2.32 UA1.2 | length 1425.4
  Top Layer w10: P6.8@-314.43,1800.14 -314.43,1788.14 -250.68,1724.4 U2.32@-250.68,1482.66
  Top Layer w20: v2(-1128.15,1999.8) -1145.28,2016.93 AP1.1@-1145.28,2049.21 -1123.69,2070.8 UA1.2@-1123.69,2168.9
  Bottom Layer w10: v2(-1128.15,1999.8) -1048.82,1920.47 -434.76,1920.47 P6.8@-314.43,1800.14
A_P+: A+1.1 K+A1.1 UA1.7 | length 616.5
  Top Layer w20: K+A1.1@-1524.02,2365.75 -1511.42,2353.15 A+1.1@-1511.42,2240.16 -1496.06,2224.8 -1225.2,2224.8 -1123.69,2326.31 UA1.7@-1123.69,2375.9
ADC2_CH7: C44.2 P4.1 R75.2 R76.2 U2.1 | length 3257.7
  Top Layer w10: R75.2@-1938.98,1621.65 -1632.28,1621.65 -1546.06,1535.43 v1(-1546.06,1184.65) ; v1(-1420.47,1189.37) -1420.47,1017.32 -1333.86,930.71 -1333.86,492.13 -1211.02,369.29 -966.14,369.29 -830.71,504.72 R76.2@-714.57,504.72 R76.2@-715.75,505.91 ; P4.1@-715.75,621.26 R76.2@-715.75,505.91 ; P4.1@-715.35,621.26 -690.55,621.26 -526.69,785.12 -526.69,975.67 -362.22,1140.14 U2.1@-329.43,1140.14 ; C44.2@-653.95,505.91 R76.2@-715.75,505.91
  Bottom Layer w10: v1(-1546.06,1184.65) -1425.2,1184.65 v1(-1420.47,1189.37)
AI: AL.3 P17.3 R15.1 | length 562.1
  Top Layer w20: R15.1@-871.26,2698.82 -787.4,2698.82 -734.25,2645.67 -734.25,2362.99 -775.98,2321.26 -833.46,2321.26 P17.3@-836.22,2318.5
  other v1: -822.05,2627.95 -751.57,2629.53 -878.35,2632.68 -1015.75,2634.65 -936.22,2643.31 -846.85,2654.33 -790.16,2655.91 -1016.54,2677.56 -742.13,2683.07 -938.19,2698.43 -1017.72,2727.17 -743.7,2727.17 -912.6,2735.43
AP: P17.2 RPA2.1 | length 680.2
  Top Layer w8: P17.2@-836.22,2218.5 -802.76,2218.5 -762.2,2177.95 -762.2,1723.23 -736.61,1697.64 RPA2.1@-638.19,1697.64
AX: AH.3 AL.2 C7.2 CAH1.2 P17.1 PXA1.1 R1.2 R21.1 RA1.2 UA1.6 | length 4573.3
  Top Layer w10: CAH1.2@-1385.04,2410.24 -1385.04,2414.24 ccw(c-1391.04,2414.24) -1391.04,2420.24 -1469.04,2420.24 cw(c-1469.04,2426.24) -1475.04,2426.24 -1475.04,2434.24 cw(c-1469.04,2434.24) -1469.04,2440.24 -1301.04,2440.24 ccw(c-1301.04,2446.24) -1295.04,2446.24 -1295.04,2454.24 ccw(c-1301.04,2454.24) -1301.04,2460.24 -1469.04,2460.24 cw(c-1469.04,2466.24) -1475.04,2466.24 -1475.04,2474.24 cw(c-1469.04,2474.24) -1469.04,2480.24 -1301.04,2480.24 ccw(c-1301.04,2486.24) -1295.04,2486.24 -1295.04,2494.24 ccw(c-1301.04,2494.24) -1301.04,2500.24 -1469.04,2500.24 cw(c-1469.04,2506.24) -1475.04,2506.24 -1475.04,2514.24 cw(c-1469.04,2514.24) -1469.04,2520.24 -1301.04,2520.24 ccw(c-1301.04,2526.24) -1295.04,2526.24 -1295.04,2534.24 ccw(c-1301.04,2534.24) -1301.04,2540.24 -1469.04,2540.24 cw(c-1469.04,2546.24) -1475.04,2546.24 -1475.04,2554.24 cw(c-1469.04,2554.24) -1469.04,2560.24 -1301.04,2560.24 ccw(c-1301.04,2566.24) -1295.04,2566.24 -1295.04,2574.24 ccw(c-1301.04,2574.24) -1301.04,2580.24 -1469.04,2580.24 cw(c-1469.04,2586.24) -1475.04,2586.24 -1475.04,2594.24 cw(c-1469.04,2594.24) -1469.04,2600.24 -1301.04,2600.24 ccw(c-1301.04,2606.24) -1295.04,2606.24 -1295.04,2614.24 ccw(c-1301.04,2614.24) -1301.04,2620.24 -1469.04,2620.24 cw(c-1469.04,2626.24) -1475.04,2626.24 -1475.04,2634.24 cw(c-1469.04,2634.24) -1469.04,2640.24 -1301.04,2640.24 ccw(c-1301.04,2646.24) -1295.04,2646.24 -1295.04,2654.24 ccw(c-1301.04,2654.24) -1301.04,2660.24 -1469.04,2660.24 cw(c-1469.04,2666.24) -1475.04,2666.24 -1475.04,2674.24 cw(c-1469.04,2674.24) -1469.04,2680.24 -1391.04,2680.24 ccw(c-1391.04,2686.24) -1385.04,2686.24 -1385.04,2698.03 PXA1.1@-1362.6,2720.47
  Top Layer w20: AH.3@-1555.06,2668.06 AH.3@-1568.11,2681.1 -1474.99,2681.1 ; -1475.04,2698.24 cw(c-1463.04,2698.24) -1463.04,2710.24 PXA1.1@-1396.46,2710.24 ; PXA1.1@-1454.99,2681.1 PXA1.1@-1369.68,2737.01 ; PXA1.1@-1396.85,2686.22 PXA1.1@-1385.04,2698.03 ; CAH1.2@-1385.04,2410.24 -1303.15,2410.24 -1277.17,2436.22 -1105.91,2436.22 -1075.59,2405.91 -1075.59,2377.8 -1073.69,2375.9 -1073.69,2337.47 -1003.15,2266.93 -951.57,2266.93 -930.31,2245.67 -930.31,2144.49 -903.54,2117.72 -837.01,2117.72 P17.1@-836.22,2118.5 R1.2@-836.22,2023.43 ; PXA1.1@-1376.18,2730.51 PXA1.1@-1385.04,2721.65 ; PXA1.1@-1362.6,2720.47 -1150,2933.07 -1122.83,2933.07 AL.2@-1061.81,2994.09 ; PXA1.1@-1396.46,2710.24 ccw(c-1396.46,2721.65) PXA1.1@-1385.04,2721.65 ; PXA1.1@-1396.46,2710.24 ccw(c-1396.46,2721.65) PXA1.1@-1385.04,2721.65
  Top Layer w30: C7.2@-1555.06,2510.11 AH.3@-1555.06,2668.06 ; AL.2@-1061.81,2994.09 RA1.2@-897.24,2994.09
  other v1: -1611.42,2631.1 -1551.42,2631.1 -1491.42,2631.1 -1431.42,2631.1 -1371.42,2631.1 -1235.83,2661.02 -1609.84,2662.6 -1549.84,2662.6 -1489.84,2662.6 -1429.84,2662.6 -1369.84,2662.6 -1609.84,2700.79 -1549.84,2700.79 -1489.84,2700.79 -1429.84,2700.79 -1240.16,2716.14 -1608.66,2733.86 -1548.66,2733.86 -1488.66,2733.86 -1428.66,2733.86 -1241.34,2762.99 -1244.09,2809.45 -1184.09,2809.45 -1124.09,2809.45 -1064.09,2809.45 -1004.09,2809.45 -1244.09,2855.91 -1184.09,2855.91 -1124.09,2855.91 -1064.09,2855.91 -1004.09,2855.91 -1244.88,2903.94 -1184.88,2903.94 -1124.88,2903.94 -1064.88,2903.94 -1004.88,2903.94 -1303.54,2951.18 -1244.49,2953.15 -1184.49,2953.15 -1124.49,2953.15 -1064.49,2953.15 -1004.49,2953.15 -1246.46,2996.85 -1186.46,2996.85 -1126.46,2996.85 -1066.46,2996.85 -1006.46,2996.85 -1277.17,3038.98 -1224.02,3041.34 -1164.02,3041.34 -1104.02,3041.34 -1044.02,3041.34 -984.02,3041.34
  other v3: -1445.68,2837.01 -1293.68,2837.01
B_N: BN1.1 P6.5 U2.29 UB1.3 | length 792.8
  Top Layer w10: U2.29@-191.63,1482.66 -191.63,1656.94 -107.43,1741.14 -73.43,1741.14 P6.5@-14.43,1800.14 ; UB1.3@-49.21,2167.72 UB1.3@-49.21,2151.97 -49.21,2035.04 -41.73,2027.56 v1(-41.73,1927.56)
  Bottom Layer w10: v1(-41.73,1927.56) -41.73,1827.45 P6.5@-14.43,1800.14
B_N-: B-1.1 K-B1.2 UB1.5 | length 243.4
  Top Layer w20: K-B1.2@-73.23,2488.39 -57.28,2488.39 0.79,2430.31 0.79,2374.72 49.13,2326.38 B-1.1@70.47,2326.38
B_P: BP1.1 P6.6 U2.30 UB1.2 | length 757
  Top Layer w10: U2.30@-211.31,1482.66 -211.31,1703.25 P6.6@-114.43,1800.14 ; v1(-145.28,1929.13) BP1.1@-145.28,2024.02 -99.21,2070.08 UB1.2@-99.21,2167.72
  Bottom Layer w10: v1(-145.28,1929.13) -145.28,1830.99 P6.6@-114.43,1800.14
B_P+: B+1.1 K+B1.1 UB1.7 | length 638.6
  Top Layer w20: K+B1.1@-543.31,2324.41 -542.13,2323.23 B+1.1@-542.13,2243.31 -511.02,2212.2 -203.94,2212.2 -99.21,2316.93 UB1.7@-99.21,2374.72
BI: BL.3 P18.3 R16.2 | length 524.1
  Top Layer w20: P18.3@170.08,2338.19 269.69,2338.19 307.09,2375.59 307.09,2600.79 R16.2@203.54,2704.33
  other v1: -26.38,2644.49 33.62,2644.49 93.62,2644.49 153.62,2644.49 213.62,2644.49 120.47,2662.6 -25.59,2689.76 34.41,2689.76 94.41,2689.76 154.41,2689.76 214.41,2689.76 -25.59,2737.01 34.41,2737.01 94.41,2737.01 154.41,2737.01 214.41,2737.01
BP: P18.2 RPB2.1 | length 1198.9
  Top Layer w10: P18.2@170.08,2238.19 311.75,2238.19 684.57,1865.37 684.57,1517.64 601.97,1435.04 538.11,1435.04 RPB2.1@537.01,1433.94
BX: BH.3 BL.2 C16.2 CBH1.2 P18.1 PXB1.1 R2.2 R39.1 RB1.2 UB1.6 | length 4769.2
  Top Layer w10: CBH1.2@-346.85,2396.85 -346.85,2400.85 ccw(c-352.85,2400.85) -352.85,2406.85 -430.85,2406.85 cw(c-430.85,2412.85) -436.85,2412.85 -436.85,2420.85 cw(c-430.85,2420.85) -430.85,2426.85 -262.85,2426.85 ccw(c-262.85,2432.85) -257.49,2430.15 ccw(c-262.85,2432.85) -256.85,2432.85 -256.85,2440.85 ccw(c-262.85,2440.85) -262.85,2446.85 -430.85,2446.85 cw(c-430.85,2452.85) -436.85,2452.85 -436.85,2460.85 cw(c-430.85,2460.85) -430.85,2466.85 -262.85,2466.85 ccw(c-262.85,2472.85) -256.85,2472.85 -256.85,2480.85 ccw(c-262.85,2480.85) -262.85,2486.85 -430.85,2486.85 cw(c-430.85,2492.85) -436.85,2492.85 -436.85,2500.85 cw(c-430.85,2500.85) -430.85,2506.85 -262.85,2506.85 ccw(c-262.85,2512.85) -256.85,2512.85 -256.85,2520.85 ccw(c-262.85,2520.85) -262.85,2526.85 -430.85,2526.85 cw(c-430.85,2532.85) -436.85,2532.85 -436.85,2540.85 cw(c-430.85,2540.85) -430.85,2546.85 -262.85,2546.85 ccw(c-262.85,2552.85) -256.85,2552.85 -256.85,2560.85 ccw(c-262.85,2560.85) -262.85,2566.85 -430.85,2566.85 cw(c-430.85,2572.85) -436.85,2572.85 -436.85,2580.85 cw(c-430.85,2580.85) -430.85,2586.85 -262.85,2586.85 ccw(c-262.85,2592.85) -256.85,2592.85 -256.85,2600.85 ccw(c-262.85,2600.85) -262.85,2606.85 -430.85,2606.85 cw(c-430.85,2612.85) -436.85,2612.85 -436.85,2620.85 cw(c-430.85,2620.85) -430.85,2626.85 -285.51,2626.85 -262.85,2626.85 ccw(c-262.85,2632.85) -256.85,2632.85 -256.85,2640.85 ccw(c-262.85,2640.85) -262.85,2646.85 -305.51,2646.85 -430.85,2646.85 cw(c-430.85,2652.85) -436.85,2652.85 -436.85,2660.85 cw(c-430.85,2660.85) -430.85,2666.85 -346.68,2666.85 -325.51,2666.85 -262.85,2666.85 ccw(c-262.85,2672.85) -256.85,2672.85 -256.85,2680.85 ccw(c-262.85,2680.85) -262.85,2686.85 -345.51,2686.85 -346.85,2686.85 -346.85,2687.4 -346.46,2687.79 PXB1.1@-331.69,2702.56
  Top Layer w20: C16.2@-564.8,2492.71 -564.8,2595.83 BH.3@-479.53,2681.1 -353.15,2681.1 PXB1.1@-346.85,2687.4 ; CBH1.2@-346.85,2396.85 -259.84,2396.85 -226.54,2430.15 -64.4,2430.15 -49.21,2414.96 UB1.6@-49.21,2358.97 -49.21,2307.09 -19.68,2277.56 70.47,2277.56 96.06,2251.97 96.06,2165.75 123.62,2138.19 P18.1@170.08,2138.19 170.08,2044.69 R2.2@169.88,2044.49 ; PXB1.1@-346.85,2686.85 -346.85,2668.85 ccw(c-334.85,2668.85) -346.68,2666.85 ccw(c-334.85,2668.85) -334.85,2656.85 PXB1.1@-315.51,2656.85 ; PXB1.1@-346.46,2687.79 -345.51,2686.85 -325.51,2666.85 PXB1.1@-315.51,2656.85 ; PXB1.1@-331.69,2702.56 -103.94,2930.31 BL.2@-103.94,2933.07 ; -268.85,2616.85 ccw(c-268.85,2628.85) -259.1,2621.85 ; -256.85,2632.85 -256.85,2628.85 cw(c-268.85,2628.85) -259.1,2621.85 ; PXB1.1@-256.85,2640.85 -256.85,2644.85 ccw(c-268.85,2644.85) -268.85,2656.85 PXB1.1@-315.51,2656.85 ; -251.41,2621.85 -259.1,2621.85 ; PXB1.1@-315.51,2656.85 -305.51,2646.85 -285.51,2626.85 -280.51,2621.85 -259.1,2621.85
  Top Layer w30: BL.2@-60.24,2933.07 11.89,3005.2 RB1.2@107.93,3005.2
  other v1: -549.61,2634.65 -489.61,2634.65 -429.61,2634.65 -550.79,2679.53 -490.79,2679.53 -430.79,2679.53 -552.76,2721.65 -492.76,2721.65 -432.76,2721.65 -99.21,2796.46 -181.5,2816.14 -121.5,2816.14 -61.5,2816.14 -1.5,2816.14 58.5,2816.14 -191.34,2860.63 -131.34,2860.63 -71.34,2860.63 -11.34,2860.63 48.66,2860.63 -190.16,2914.17 -130.16,2914.17 -70.16,2914.17 -10.16,2914.17 49.84,2914.17 -189.76,2965.75 -129.76,2965.75 -69.76,2965.75 -9.76,2965.75 50.24,2965.75 -186.61,3004.72 -126.61,3004.72 -66.61,3004.72 -6.61,3004.72 53.39,3004.72 -342.91,3049.21 -225.59,3050.79 44.88,3051.57 -283.46,3051.97 -181.5,3051.97 -121.5,3051.97 -61.5,3051.97 -1.5,3051.97
  other v3: -379.15,2837.01 -227.15,2837.01
C_N: CN1.1 P6.3 U2.27 UC1.3 | length 1598
  Top Layer w10: U2.27@-152.26,1482.66 -152.26,1613.09 -96.21,1669.14 54.57,1669.14 P6.3@185.57,1800.14 ; v1(648.03,1962.2) 948.82,1962.2 985.83,1999.21 CN1.1@985.83,2037.01 986.22,2037.4 UC1.3@986.22,2168.11
  Bottom Layer w10: P6.3@185.57,1800.14 267.4,1881.97 566.61,1881.97 v1@648.03,1963.39
C_N-: C-1.1 K-C1.2 UC1.5 | length 198.6
  Top Layer w20: K-C1.2@1008.27,2479.33 1036.22,2451.38 1036.22,2375.11 1075.5,2335.83 C-1.1@1102.76,2335.83
C_P: CP1.1 P6.4 U2.28 UC1.2 | length 1542.6
  Top Layer w10: U2.28@-171.94,1482.66 -171.94,1627.62 -95.43,1704.14 -10.43,1704.14 P6.4@85.57,1800.14 ; v1(610.24,1990.16) 838.98,1990.16 CP1.1@888.58,2039.76 936.22,2087.4 UC1.2@936.22,2168.11
  Bottom Layer w10: P6.4@103.57,1800.14 P6.4@85.57,1800.14 187.4,1901.97 521.26,1901.97 v1@610.24,1990.94
C_P+: C+1.1 K+C1.1 UC1.7 | length 650.9
  Top Layer w20: K+C1.1@487.4,2348.82 487.4,2259.84 C+1.1@487.8,2259.45 528.74,2218.5 832.68,2218.5 936.22,2322.05 UC1.7@936.22,2375.11
CI: CL.3 P19.3 R17.1 | length 577.4
  Top Layer w20: P19.3@1203.54,2315.75 1314.57,2315.75 1367.32,2368.5 1367.32,2569.29 R17.1@1232.28,2704.33
  other v1: 1192.91,2639.37 1251.18,2642.13 1298.43,2642.52 1022.44,2644.49 1082.44,2644.49 1142.44,2644.49 1020.87,2684.25 1080.87,2684.25 1140.87,2684.25 1132.28,2707.48 1020.08,2729.13 1080.08,2729.13 1140.08,2729.13
CP: P19.2 RPC2.1 | length 1739.9
  Top Layer w10: RPC2.1@548.43,1196.85 691.73,1196.85 765.67,1270.79 765.67,1832.2 792.91,1859.45 1239.37,1859.45 1305.12,1925.2 1305.12,2148.43 1263.07,2190.47 1228.82,2190.47 P19.2@1203.54,2215.75
CX: C24.2 CCH1.2 CH.3 CL.2 P19.1 PXC1.1 R3.2 R50.1 RC1.2 UC1.6 | length 4230
  Top Layer w10: CCH1.2@690.95,2405.9 690.95,2409.9 ccw(c684.95,2409.9) 690.81,2411.15 ccw(c684.95,2409.9) 684.95,2415.9 606.95,2415.9 cw(c606.95,2421.9) 600.95,2421.9 600.95,2429.9 cw(c606.95,2429.9) 606.95,2435.9 774.95,2435.9 ccw(c774.95,2441.9) 780.95,2441.9 780.95,2449.9 ccw(c774.95,2449.9) 774.95,2455.9 606.95,2455.9 cw(c606.95,2461.9) 600.95,2461.9 600.95,2469.9 cw(c606.95,2469.9) 606.95,2475.9 774.95,2475.9 ccw(c774.95,2481.9) 780.95,2481.9 780.95,2489.9 ccw(c774.95,2489.9) 774.95,2495.9 606.95,2495.9 cw(c606.95,2501.9) 600.95,2501.9 600.95,2509.9 cw(c606.95,2509.9) 606.95,2515.9 774.95,2515.9 ccw(c774.95,2521.9) 780.95,2521.9 780.95,2529.9 ccw(c774.95,2529.9) 774.95,2535.9 606.95,2535.9 cw(c606.95,2541.9) 600.95,2541.9 600.95,2549.9 cw(c606.95,2549.9) 606.95,2555.9 774.95,2555.9 ccw(c774.95,2561.9) 780.95,2561.9 780.95,2569.9 ccw(c774.95,2569.9) 774.95,2575.9 606.95,2575.9 cw(c606.95,2581.9) 600.95,2581.9 600.95,2589.9 cw(c606.95,2589.9) 606.95,2595.9 774.95,2595.9 ccw(c774.95,2601.9) 780.95,2601.9 780.95,2609.9 ccw(c774.95,2609.9) 774.95,2615.9 606.95,2615.9 cw(c606.95,2621.9) 600.95,2621.9 600.95,2629.9 cw(c606.95,2629.9) 606.95,2635.9 774.95,2635.9 ccw(c774.95,2641.9) 780.95,2641.9 780.95,2649.9 ccw(c774.95,2649.9) 774.95,2655.9 606.95,2655.9 cw(c606.95,2661.9) 600.95,2661.9 600.95,2669.9 cw(c606.95,2669.9) 606.95,2675.9 684.95,2675.9 ccw(c684.95,2681.9) 690.95,2681.9 690.95,2688.19 PXC1.1@717.32,2714.57
  Top Layer w20: C24.2@464.39,2503.79 464.39,2600.21 CH.3@545.28,2681.1 551.97,2687.79 690.55,2687.79 PXC1.1@690.95,2688.19 ; CCH1.2@690.55,2421.65 CCH1.2@690.95,2405.9 772.83,2405.9 788.58,2421.65 974.41,2421.65 986.22,2409.84 UC1.6@986.22,2357.39 986.22,2334.25 1034.65,2285.83 1107.48,2285.83 1130.71,2262.6 1130.71,2142.91 1158.66,2114.96 1159.45,2115.75 P19.1@1203.54,2115.75 R3.2@1203.54,2020.47 ; PXC1.1@690.95,2681.9 690.95,2677.9 ccw(c702.95,2677.9) PXC1.1@702.95,2665.9 ; PXC1.1@717.32,2714.57 935.83,2933.07 CL.2@954.33,2933.07
  Top Layer w30: 1098.43,3007.09 1098.82,3007.48 RC1.2@1159.06,3007.48
  other v1: 464.17,2641.34 524.17,2641.34 584.17,2641.34 465.75,2689.76 525.75,2689.76 585.75,2689.76 462.6,2740.16 522.6,2740.16 582.6,2740.16 905.51,2795.67 831.89,2838.98 891.89,2838.98 951.89,2838.98 1011.89,2838.98 1071.89,2838.98 828.74,2893.31 888.74,2893.31 948.74,2893.31 1008.74,2893.31 1068.74,2893.31 827.17,2952.76 887.17,2952.76 947.17,2952.76 1007.17,2952.76 1067.17,2952.76 820.08,3004.72 880.08,3004.72 940.08,3004.72 1000.08,3004.72 1060.08,3004.72 655.12,3050.39 724.8,3050.39 784.8,3050.39 844.8,3050.39 904.8,3050.39 964.8,3050.39
  other v3: 637.39,2837.01 789.39,2837.01
DM_IN: DD6.1 DM_IN.1 R74.1 | length 536.9
  Top Layer w20: -2101.57,1569.68 -2099.61,1567.72 R74.1@-1999.61,1567.72
  Top Layer w40: -2280.71,1424.41 -2279.44,1423.14 DD6.1@-2279.44,1275.84 ; v1@-2251.03,1479.28 -2251.03,1565.11 DM_IN.1@-2242.52,1573.62 ; v1@-2249.85,1478.1 -2130.56,1478.1 -2107.09,1501.57 -2107.09,1536.22
  other v1: -2253.54,1432.68 -2196.85,1432.68 -2130.31,1432.68 -2315.35,1448.82 -2253.54,1480.31 -2175.98,1481.1 -2119.29,1483.86 -2315.35,1490.55 -2124.02,1533.07 -2171.26,1537.8 -2313.39,1541.73 -2318.11,1590.94 -2168.5,1602.36 -2117.32,1607.87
